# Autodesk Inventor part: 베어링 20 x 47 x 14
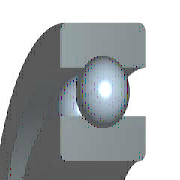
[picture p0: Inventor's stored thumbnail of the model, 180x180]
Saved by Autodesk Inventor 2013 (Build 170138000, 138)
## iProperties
IsCustomPart: 1
Created: 2012-02
Part Number: 베어링 20 x 47 x 14
Material: 강철, 연강
Description: 깊은 그루브 볼 베어링
Document SubType Name: Modeling
Standard: KS B 2023
Designer: mduedu
Standards Organization: KS
Language: ko-KR
Size Designation: 6204 - 20 x 47 x 14
Categories: <MemberInstance><Categories><Category DisplayName="샤프트 부품" InternalName="7f7aeb1f-a693-4053-b835-cee3144e0d98" Mnemonic="SHFT"><Category DisplayName="베어링" Inter
Density: 7.86 g/cm^3
Mass: 104.255 g
Surface Area: 87.8912 cm^2
Volume: 13.264 cm^3
Author: mduedu
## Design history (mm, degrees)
sketch "스케치" dims "d0" = 7.02 (= -0.26 x WD + 0.26 x BD)
  geometry: L1 (3.49, 16.75)-(10.51, 16.75); L2 (7, 16.75)-(7, 13.24); L3 (7, 16.75)-(7, 20.26); L4 (4.392, 14.401)-(0, 14.401); L5 (0, 10)-(14, 10); L6 (4.392, 19.099)-(0, 19.099); L7 (0, 23.5)-(14, 23.5); L8 (14, 10)-(14, 14.401); L9 (9.608, 14.401)-(14, 14.401); L10 (9.608, 19.099)-(14, 19.099); L11 (14, 23.5)-(14, 19.099); L12 (-1.4, 0)-(8.4, 0) reference; L13 (0, -0.3)-(0, 5.3) reference
  constraints: 22 end point, 4 point on line, 2 collinear, 2 perpendicular, 2 symmetric about line, 1 midpoint, 1 parallel, 14 other
  dimensions: "d9" = 20 diameter of L5 L12 (= WD); "d11" = 47 diameter of L7 L12 (= BD); "d12" = 14 distance between parallel lines of L8 L13 (= KB); "d13" = 28.802 diameter of L9 L12 (= 0.326 x BD + 0.674 x WD)
revolve "본체" stored, may be unused: angle "d6" = 90 deg
revolve "볼" stored, may be unused: angle "d7" = 90 deg
pattern_circular "IDS_ARRAYBALL[SIMPL:T]" dims angle "d3" = 360 deg
body "Solid1"
fillet "모깎기1" dims "d1" = 1 (= KRS)
other parameters: "WD" = 20 [user parameter; used in 5 equation terms], "BD" = 47 [user parameter; used in 5 equation terms], "KB" = 14 [user parameter; used in 1 equation term], "KRS" = 1 [user parameter; used in 1 equation term], "d4" = 0, "d5" = 0, "d8" = 0, "d14" = 0, "d15" = 0, "BBA" = 0 [user parameter], "BC0" = 6550000 [user parameter], "BC" = 1.27e+07 [user parameter], "BR" = 23.5 (= 0.5 x BD) [user parameter]
